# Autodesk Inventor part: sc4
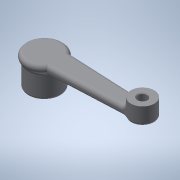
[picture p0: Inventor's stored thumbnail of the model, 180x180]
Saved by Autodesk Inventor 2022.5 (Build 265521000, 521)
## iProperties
Created: 2016-12
Part Number: sc4
Material: 一般
Document SubType Name: Modeling
Designer: imaocorp
Density: 1 g/cm^3
Appearance: 既定
Author: imaocorp
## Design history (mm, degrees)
node "sc4.x_t1"
node "sc4"
node "Base1"
